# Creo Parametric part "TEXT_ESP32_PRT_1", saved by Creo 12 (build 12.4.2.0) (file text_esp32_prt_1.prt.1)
Units: Custom; MM, KILOGRAM, SECS

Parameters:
  PTC_WM_ITERATION = "0"
  PTC_WM_VERSION = "-.0"
  PTC_WM_LIFECYCLE_STATE = "In Work"
  PTC_WM_LIFECYCLE = "MO_CADDocument"
  PTC_WM_CREATED_BY = "Maximilian Roepper (Z0017RMS: MO)"
  PTC_WM_CREATED_ON = "18-Sep-26 11:36:42 AM"
  PTC_WM_MODIFIED_BY = "Maximilian Roepper (Z0017RMS: MO)"
  PTC_WM_MODIFIED_ON = "18-Sep-26 11:36:46 AM"
  PDMLINKNUMBER = "PDM000071454917"
  PTC_WM_NAME = "text_esp32_prt_1.prt"
  PTC_WM_NUMBER = "PDM000071454917"

Other parameters: WEIGHT, WEIGHT_FACTOR, WEIGHT_ADD, _MASS_TEMP, _DIFF_TEMP, MC_ERRORS, SUPPLIER

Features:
  1. coordinate system
  2. datum plane "PRT_YZ"
  3. datum plane "PRT_XY"
  4. datum plane "PRT_XZ"
  5. coordinate system
  6. datum axis
  7. datum axis
  8. datum axis
  9. coordinate system
  10. imported feature
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
Other named items: PRT, SIEMENS_MO, DRW_VIEW_ORG, PRT_X, PRT_Y, PRT_Z, CS0, ROUGH_GROB

Layers: 00_STD_CSYS-KSYS, 01_STD_PLANES-EBENEN, 02_STD_AXES-ACHSEN, 03_STD_CSYS-KSYS, 24_IMPORT_FEAT-IMPORT_KE

Surfaces: 14 plane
